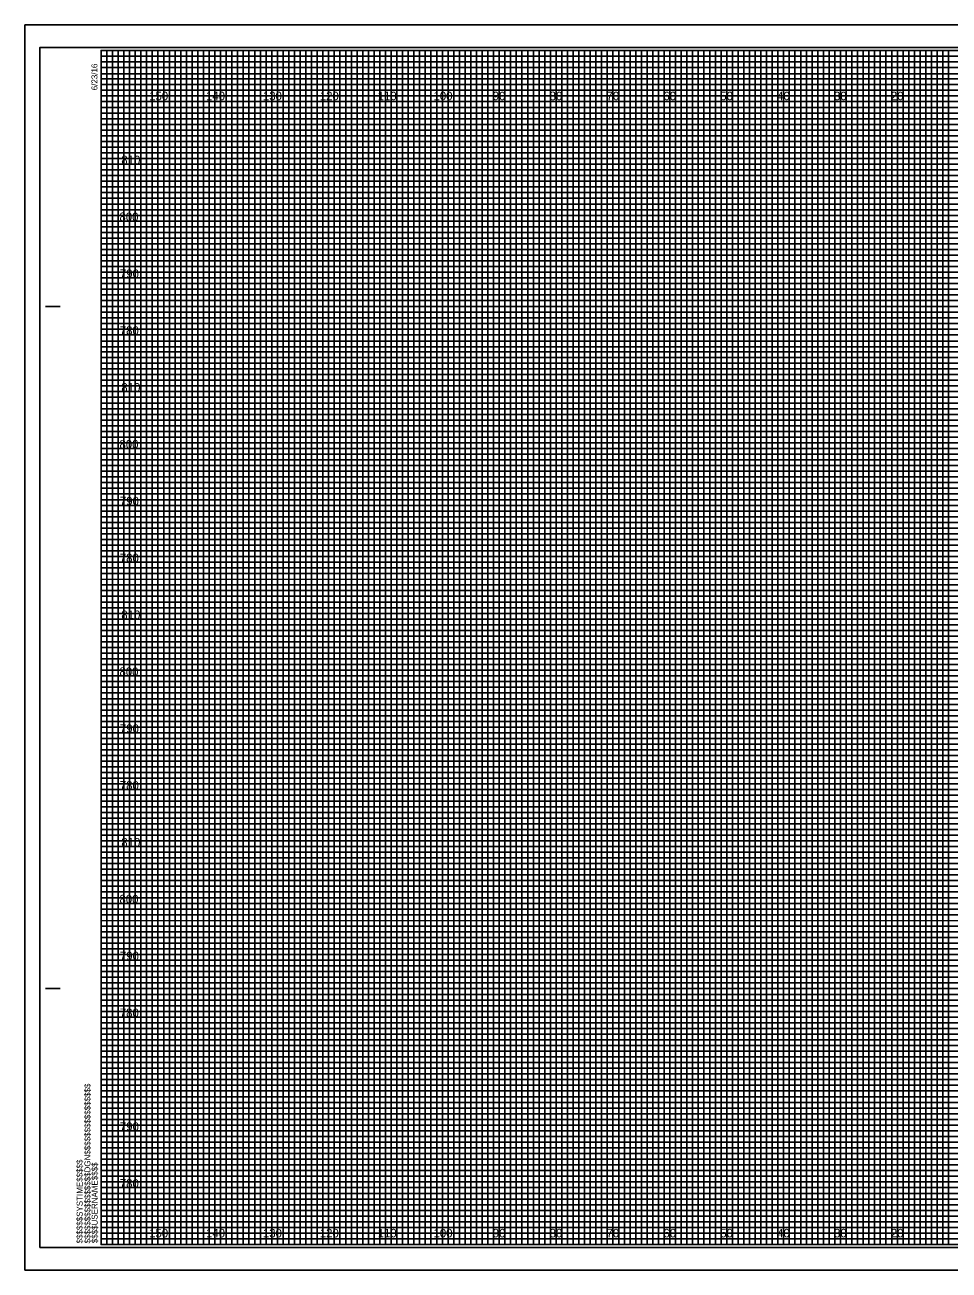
# Model space of a CAD drawing. Extents: x -13 to 323, y -4 to 214.
# Drawn here: x -13.4 to 149.1, y -4.5 to 214.5 of the extents above; entities that cross this region are included whole.
import ezdxf

# ---------------------------------------------------------------- set-up
doc = ezdxf.new("R2010")
doc.units = 0
for name, color, linetype in [('Exist Cross Section Cell', 7, 'Continuous'), ('Exist XS Center Line Elevation Label', 7, 'Continuous'), ('Exist XS Ground Line', 7, 'Continuous'), ('Prop CMT Conc Surface', 7, 'Continuous'), ('Prop CMT Concrete Structures', 7, 'Continuous'), ('Prop CMT Pvmt Course 1', 7, 'Continuous'), ('Prop CMT Pvmt Course 1 CG', 7, 'Continuous'), ('Prop CMT Pvmt Course 2', 7, 'Continuous'), ('Prop CMT Pvmt Course 3', 7, 'Continuous'), ('Prop CMT Pvmt Surface', 7, 'Continuous'), ('Prop XS Shear Point Element', 7, 'Continuous')]:
    doc.layers.add(name, color=color, linetype=linetype)

msp = doc.modelspace()

# ---------------------------------------------------------------- linework, layer by layer
at = {"layer": 'Exist XS Center Line Elevation Label'}
for points in [[(0, 210), (5, 210), (5, 0), (15, 0), (15, 210), (25, 210), (25, 0), (35, 0), (35, 210), (45, 210), (45, 0), (55, 0), (55, 210), (65, 210), (65, 0), (75, 0), (75, 210), (85, 210), (85, 0), (95, 0), (95, 210), (105, 210), (105, 0), (115, 0), (115, 210), (125, 210), (125, 0), (135, 0), (135, 210), (145, 210), (145, 0), (155, 0)], [(0, 205), (275, 205)], [(0, 185), (320, 185), (320, 195), (0, 195)], [(0, 165), (320, 165), (320, 175), (0, 175)], [(0, 145), (320, 145), (320, 155), (0, 155)], [(0, 125), (320, 125), (320, 135), (0, 135)], [(0, 105), (320, 105), (320, 115), (0, 115)], [(0, 85), (320, 85), (320, 95), (0, 95)], [(0, 65), (320, 65), (320, 75), (0, 75)], [(0, 45), (320, 45), (320, 55), (0, 55)], [(0, 25), (320, 25), (320, 35), (0, 35)], [(0, 5), (320, 5), (320, 15), (0, 15)]]:
    msp.add_lwpolyline(points, dxfattribs=at)
at = {"layer": 'Exist XS Ground Line'}
for p, q in [((10, 210), (0, 210)), ((10, 0), (10, 210)), ((30, 210), (20, 210)), ((20, 210), (20, 0)), ((30, 0), (30, 210)), ((50, 210), (40, 210)), ((40, 210), (40, 0)), ((50, 0), (50, 210)), ((70, 210), (60, 210)), ((60, 210), (60, 0)), ((70, 0), (70, 210)), ((90, 210), (80, 210)), ((80, 210), (80, 0)), ((90, 0), (90, 210)), ((110, 210), (100, 210)), ((100, 210), (100, 0)), ((110, 0), (110, 210)), ((130, 210), (120, 210)), ((120, 210), (120, 0)), ((130, 0), (130, 210)), ((150, 210), (140, 210)), ((140, 210), (140, 0)), ((20, 0), (10, 0)), ((40, 0), (30, 0)), ((60, 0), (50, 0)), ((80, 0), (70, 0)), ((100, 0), (90, 0)), ((120, 0), (110, 0)), ((140, 0), (130, 0))]:
    msp.add_line(p, q, dxfattribs=at)
for points in [[(0, 200), (320, 200), (320, 190), (0, 190)], [(0, 180), (320, 180), (320, 170), (0, 170)], [(0, 160), (320, 160), (320, 150), (0, 150)], [(0, 140), (320, 140), (320, 130), (0, 130)], [(0, 120), (320, 120), (320, 110), (0, 110)], [(0, 100), (320, 100), (320, 90), (0, 90)], [(0, 80), (320, 80), (320, 70), (0, 70)], [(0, 60), (320, 60), (320, 50), (0, 50)], [(0, 40), (320, 40), (320, 30), (0, 30)], [(0, 20), (320, 20), (320, 10), (0, 10)]]:
    msp.add_lwpolyline(points, dxfattribs=at)
at = {"layer": 'Prop CMT Conc Surface'}
for p, q in [((323.3, 214.5), (-13.4, 214.5)), ((-13.4, 214.5), (-13.4, -4.5)), ((-13.4, -4.5), (323.3, -4.5))]:
    msp.add_line(p, q, dxfattribs=at)
at = {"layer": 'Prop CMT Concrete Structures'}
for points in [[(0, 0), (1, 0), (1, 210), (2, 210), (2, 0)], [(2, 0), (3, 0), (3, 210), (4, 210), (4, 0)], [(5, 0), (6, 0), (6, 210), (7, 210), (7, 0)], [(7, 0), (8, 0), (8, 210), (9, 210), (9, 0)], [(10, 0), (11, 0), (11, 210), (12, 210), (12, 0)], [(12, 0), (13, 0), (13, 210), (14, 210), (14, 0)], [(15, 0), (16, 0), (16, 210), (17, 210), (17, 0)], [(17, 0), (18, 0), (18, 210), (19, 210), (19, 0)], [(20, 0), (21, 0), (21, 210), (22, 210), (22, 0)], [(22, 0), (23, 0), (23, 210), (24, 210), (24, 0)], [(25, 0), (26, 0), (26, 210), (27, 210), (27, 0)], [(27, 0), (28, 0), (28, 210), (29, 210), (29, 0)], [(30, 0), (31, 0), (31, 210), (32, 210), (32, 0)], [(32, 0), (33, 0), (33, 210), (34, 210), (34, 0)], [(35, 0), (36, 0), (36, 210), (37, 210), (37, 0)], [(37, 0), (38, 0), (38, 210), (39, 210), (39, 0)], [(40, 0), (41, 0), (41, 210), (42, 210), (42, 0)], [(42, 0), (43, 0), (43, 210), (44, 210), (44, 0)], [(45, 0), (46, 0), (46, 210), (47, 210), (47, 0)], [(47, 0), (48, 0), (48, 210), (49, 210), (49, 0)], [(50, 0), (51, 0), (51, 210), (52, 210), (52, 0)], [(52, 0), (53, 0), (53, 210), (54, 210), (54, 0)], [(55, 0), (56, 0), (56, 210), (57, 210), (57, 0)], [(57, 0), (58, 0), (58, 210), (59, 210), (59, 0)], [(60, 0), (61, 0), (61, 210), (62, 210), (62, 0)], [(62, 0), (63, 0), (63, 210), (64, 210), (64, 0)], [(65, 0), (66, 0), (66, 210), (67, 210), (67, 0)], [(67, 0), (68, 0), (68, 210), (69, 210), (69, 0)], [(70, 0), (71, 0), (71, 210), (72, 210), (72, 0)], [(72, 0), (73, 0), (73, 210), (74, 210), (74, 0)], [(75, 0), (76, 0), (76, 210), (77, 210), (77, 0)], [(77, 0), (78, 0), (78, 210), (79, 210), (79, 0)], [(80, 0), (81, 0), (81, 210), (82, 210), (82, 0)], [(82, 0), (83, 0), (83, 210), (84, 210), (84, 0)], [(85, 0), (86, 0), (86, 210), (87, 210), (87, 0)], [(87, 0), (88, 0), (88, 210), (89, 210), (89, 0)], [(90, 0), (91, 0), (91, 210), (92, 210), (92, 0)], [(92, 0), (93, 0), (93, 210), (94, 210), (94, 0)], [(95, 0), (96, 0), (96, 210), (97, 210), (97, 0)], [(97, 0), (98, 0), (98, 210), (99, 210), (99, 0)], [(100, 0), (101, 0), (101, 210), (102, 210), (102, 0)], [(102, 0), (103, 0), (103, 210), (104, 210), (104, 0)], [(105, 0), (106, 0), (106, 210), (107, 210), (107, 0)], [(107, 0), (108, 0), (108, 210), (109, 210), (109, 0)], [(110, 0), (111, 0), (111, 210), (112, 210), (112, 0)], [(112, 0), (113, 0), (113, 210), (114, 210), (114, 0)], [(115, 0), (116, 0), (116, 210), (117, 210), (117, 0)], [(117, 0), (118, 0), (118, 210), (119, 210), (119, 0)], [(120, 0), (121, 0), (121, 210), (122, 210), (122, 0)], [(122, 0), (123, 0), (123, 210), (124, 210), (124, 0)], [(125, 0), (126, 0), (126, 210), (127, 210), (127, 0)], [(127, 0), (128, 0), (128, 210), (129, 210), (129, 0)], [(130, 0), (131, 0), (131, 210), (132, 210), (132, 0)], [(132, 0), (133, 0), (133, 210), (134, 210), (134, 0)], [(135, 0), (136, 0), (136, 210), (137, 210), (137, 0)], [(137, 0), (138, 0), (138, 210), (139, 210), (139, 0)], [(140, 0), (141, 0), (141, 210), (142, 210), (142, 0)], [(142, 0), (143, 0), (143, 210), (144, 210), (144, 0)], [(145, 0), (146, 0), (146, 210), (147, 210), (147, 0)], [(147, 0), (148, 0), (148, 210), (149, 210), (149, 0)]]:
    msp.add_lwpolyline(points, dxfattribs=at)
at = {"layer": 'Prop CMT Pvmt Course 1'}
msp.add_lwpolyline([(-10.8, -0.5), (322.4, -0.5), (322.4, 210.5), (-10.8, 210.5)], close=True, dxfattribs=at)
at = {"layer": 'Prop CMT Pvmt Course 1 CG'}
msp.add_lwpolyline([(-13.4, -4.5), (323.3, -4.5), (323.3, 214.5), (-13.4, 214.5)], close=True, dxfattribs=at)
at = {"layer": 'Prop CMT Pvmt Course 2'}
for p, q in [((0, 209), (260, 209)), ((260, 207.98), (0, 207.98)), ((0, 207.98), (0, 207)), ((0, 207), (260, 207)), ((260, 205.89), (0, 205.89)), ((0, 205.89), (0, 204)), ((0, 204), (320, 204))]:
    msp.add_line(p, q, dxfattribs=at)
for points in [[(0, 203), (270, 203), (320, 203), (320, 202), (0, 202)], [(0, 201), (320, 201), (320, 199), (0, 199)], [(0, 198), (320, 198), (320, 197), (0, 196.98)], [(0, 196), (320, 196), (320, 194), (0, 194)], [(0, 193), (320, 193), (320, 192), (0, 192)], [(0, 191), (320, 191), (320, 189), (0, 189)], [(0, 188), (320, 188), (320, 187), (0, 187)], [(0, 186), (320, 186), (320, 184), (0, 184)], [(0, 183), (320, 183), (320, 182), (0, 182)], [(0, 181), (320, 181), (320, 179), (0, 179)], [(0, 178), (320, 178), (320, 177), (0, 177)], [(0, 176), (320, 176), (320, 173.95), (320, 173), (320, 172), (0, 172)], [(0, 174), (320, 174), (320, 173), (0, 173)], [(0, 171), (320, 171), (320, 169), (0, 169.03)], [(0, 169.03), (320, 169), (320, 168), (0, 168)], [(0, 167), (320, 167), (320, 166), (0, 166)], [(0, 164), (320, 164), (320, 163), (0, 163)], [(0, 162), (320, 162), (320, 161), (0, 161)], [(-0.07, 158.89), (320, 158.89), (320, 157.88), (-0.07, 157.88)], [(0, 157), (320, 157), (320, 156), (0, 156)], [(0, 154), (320, 154), (320, 153), (0, 153)], [(0, 152), (320, 152), (320, 151), (0, 151)], [(0, 149), (320, 149), (320, 148), (0, 148)], [(0, 147), (320, 147), (320, 146), (0, 146)], [(0, 144), (320, 144), (320, 143), (0, 143)], [(0, 142), (320, 142), (320, 141), (0, 141)], [(0, 139), (320, 139), (319.99, 137.98), (0, 138)], [(0, 137), (320, 137), (320, 136), (0, 136)], [(0, 134), (320, 134), (320, 133), (0, 133)], [(0, 132), (320, 132), (320, 131), (0, 131)], [(0, 129), (320, 129), (320, 128), (0, 128)], [(0, 127), (320, 127), (320, 126), (0, 126)], [(0, 124), (320, 124), (320, 123), (0, 123)], [(0, 122), (320, 122), (320, 121), (0, 121)], [(0, 119), (320, 119), (320, 118), (0, 118)], [(0, 116.99), (320.07, 116.91), (320, 116), (0, 116)], [(0, 114), (320, 114), (320, 113), (0, 113)], [(0, 112), (320, 112), (320, 111), (0, 111)], [(0, 109), (320, 109), (320, 108), (0, 108)], [(0, 107), (320, 107), (320, 106), (0, 106)], [(0, 104), (320, 104), (320, 103), (0, 103)], [(0, 102), (320, 102), (320, 101), (0, 101)], [(0, 99), (320, 99), (320, 98), (0, 98)], [(0, 97), (320, 97), (320, 96), (0, 96)], [(0, 94), (320, 94), (320, 93), (0, 93)], [(0, 92), (320, 92), (320, 91), (0, 91)], [(0, 89), (320, 89), (320, 88), (0, 88)], [(0, 87), (320, 87), (320, 86), (0, 86)], [(0, 84), (320, 84), (320, 83), (0, 83)], [(0, 82), (320, 82), (320, 81), (0, 81)], [(0, 79), (320, 79), (319.99, 77.98), (0, 78)], [(0, 77), (320, 77), (320, 76), (0, 76)], [(0, 74), (320, 74), (320, 73), (0, 73)], [(0, 72), (320, 72), (320, 71), (0, 71)], [(0, 69), (320, 69), (320, 68), (0, 68)], [(0, 67), (320, 67), (320, 66), (0, 66)], [(0, 64), (320, 64), (320, 63), (0, 63)], [(0, 62), (320, 62), (320, 61), (0, 61)], [(0, 59), (320, 59), (320, 58), (0, 58)], [(0, 56.99), (320.07, 56.91), (320, 56), (0, 56)], [(0, 54), (320, 54), (320, 53), (0, 53)], [(0, 52), (320, 52), (320, 51), (0, 51)], [(0, 49), (320, 49), (320, 48), (0, 48)], [(0, 47), (320, 47), (320, 46), (0, 46)], [(0, 44), (320, 44), (320, 43), (0, 43)], [(0, 42), (320, 42), (320, 41), (0, 41)], [(0, 39), (320, 39), (320, 38), (0, 38)], [(0, 37), (320, 37), (320, 36), (0, 36)], [(0, 34), (320, 34), (320, 33), (0, 33)], [(0, 32), (320, 32), (320, 31), (0, 31)], [(0, 29), (320, 29), (320, 28), (0, 28)], [(0, 27), (320, 27), (320, 26), (0, 26)], [(0, 24), (320, 24), (320, 23), (0, 23)], [(0, 22), (320, 22), (320, 21), (0, 21)], [(0, 19), (320, 19), (320, 18), (0, 18)], [(0, 17), (320, 17), (320, 16), (0, 16)], [(0, 14), (320, 14), (320, 13), (0, 13)], [(0, 12), (320, 12), (320, 11), (0, 11)], [(0, 9), (320, 9), (320, 8), (0, 8)], [(0, 7), (320, 7), (320, 6), (0, 6)], [(0, 4), (320, 4), (320, 3), (0, 3)], [(0, 2), (320, 2), (320, 1), (0, 1)]]:
    msp.add_lwpolyline(points, dxfattribs=at)
at = {"layer": 'Prop CMT Pvmt Course 3'}
for p, q in [((-9.8, 165), (-7.3, 165)), ((-9.7, 165), (-7.2, 165)), ((-9.8, 45), (-7.3, 45)), ((-9.7, 45), (-7.2, 45)), ((0, 0), (0, 0)), ((0, 0), (0, 0)), ((0, 0), (0, 0)), ((0, 0), (0, 0)), ((0, 0), (0, 0)), ((0, 0), (0, 0)), ((0, 0), (0, 0))]:
    msp.add_line(p, q, dxfattribs=at)
msp.add_lwpolyline([(320, 210), (0, 210), (0, 0), (320, 0)], close=True, dxfattribs=at)
at = {"layer": 'Prop XS Shear Point Element'}
for p, q in [((10, 0), (10, 210)), ((20, 0), (20, 210)), ((30, 0), (30, 210)), ((40, 0), (40, 210)), ((50, 0), (50, 210)), ((60, 0), (60, 210)), ((70, 0), (70, 210)), ((80, 0), (80, 210)), ((90, 0), (90, 210)), ((100, 0), (100, 210)), ((110, 0), (110, 210)), ((120, 0), (120, 210)), ((130, 0), (130, 210)), ((140, 0), (140, 210)), ((0, 200), (320, 200)), ((0, 190), (320, 190)), ((0, 180), (320, 180)), ((0, 170), (320, 170)), ((0, 160), (320, 160)), ((0, 150), (320, 150)), ((0, 140), (320, 140)), ((0, 130), (320, 130)), ((0, 120), (320, 120)), ((0, 110), (320, 110)), ((0, 100), (320, 100)), ((0, 90), (320, 90)), ((0, 80), (320, 80)), ((0, 70), (320, 70)), ((0, 60), (320, 60)), ((0, 50), (320, 50)), ((0, 40), (320, 40)), ((0, 30), (320, 30)), ((0, 20), (320, 20)), ((0, 10), (320, 10))]:
    msp.add_line(p, q, dxfattribs=at)

# ---------------------------------------------------------------- texts
at = {"layer": 'Exist Cross Section Cell'}
for s, p in [('150', (8.44, 201.25)), ('140', (18.44, 201.25)), ('130', (28.44, 201.25)), ('120', (38.44, 201.25)), ('110', (48.62, 201.25)), ('100', (58.44, 201.25)), ('90', (68.86, 201.25)), ('80', (78.86, 201.25)), ('70', (88.86, 201.25)), ('60', (98.86, 201.25)), ('50', (108.86, 201.25)), ('40', (118.86, 201.25)), ('30', (128.86, 201.25)), ('20', (138.86, 201.25)), ('150', (8.44, 1.25)), ('140', (18.44, 1.25)), ('130', (28.44, 1.25)), ('120', (38.44, 1.25)), ('110', (48.62, 1.25)), ('100', (58.44, 1.25)), ('90', (68.86, 1.25)), ('80', (78.86, 1.25)), ('70', (88.86, 1.25)), ('60', (98.86, 1.25)), ('50', (108.86, 1.25)), ('40', (118.86, 1.25)), ('30', (128.86, 1.25)), ('20', (138.86, 1.25))]:
    msp.add_text(s, height=1.5, dxfattribs=at).set_placement(p)
at = {"layer": 'Prop CMT Pvmt Course 3'}
for s, p in [('6/23/16', (-0.65, 203)), ('$$$$$$$$$$$$$$$$DGN$$$$$$$$$$$$$$$$', (-1.88, 0.18)), ('$$$$$$SYSTIME$$$$$', (-3.26, 0.18)), ('$$$$USERNAME$$$$', (-0.62, 0.23))]:
    msp.add_text(s, height=1.05, rotation=90, dxfattribs=at).set_placement(p)
at = {"layer": 'Prop CMT Pvmt Surface'}
for s, p in [('810', (3.55, 190)), ('800', (3.22, 180)), ('790', (3.3, 170)), ('780', (3.28, 160)), ('810', (3.55, 150)), ('800', (3.22, 140)), ('790', (3.3, 130)), ('780', (3.28, 120)), ('810', (3.55, 110)), ('800', (3.22, 100)), ('790', (3.3, 90)), ('780', (3.28, 80)), ('810', (3.55, 70)), ('800', (3.22, 60)), ('790', (3.3, 50)), ('780', (3.28, 40)), ('790', (3.3, 20)), ('780', (3.28, 10))]:
    msp.add_text(s, height=1.5, dxfattribs=at).set_placement(p)

doc.saveas('drawing.dxf')
